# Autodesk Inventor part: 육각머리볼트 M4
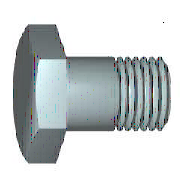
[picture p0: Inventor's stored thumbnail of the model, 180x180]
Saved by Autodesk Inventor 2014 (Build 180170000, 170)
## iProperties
IsCustomPart: 1
Created: 2012-02
Part Number: 육각머리볼트 M4
Material: 스테인리스강
Description: 6각 머리 볼트 및 6각 머리 나사
Document SubType Name: Modeling
Standard: KS B 1002
Designer: mduedu
Standards Organization: KS
Language: ko-KR
Size Designation: A + B M4 x 10
Categories: <MemberInstance><Categories><Category DisplayName="조임쇠" InternalName="e4da775c-781d-43d5-af7c-5136215cf5a6" Mnemonic="FSTN"><Category DisplayName="볼트" InternalN
Density: 8.08 g/cm^3
Mass: 1.91435 g
Surface Area: 2.70732 cm^2
Volume: 0.236925 cm^3
Appearance: 반광택
Author: mduedu
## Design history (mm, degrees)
sketch "스케치1"
  geometry: L1 (0, 2.94)-(0, 2); L2 (2.1, 2)-(10, 2); L3 (10, 2)-(10, 0); L4 (10, 0)-(-0.4, 0); L5 (-2.48, 0)-(12.08, 0) reference; L6 (-0.4, 0)-(-0.4, 2.94); L7 (-0.4, 2.94)-(0, 2.94); L8 (2.1, 2)-(1.67, 2); L9 (1.67, 2)-(0, 2); L10 (0, -0.588)-(0, 3.528) reference
  constraints: 16 end point, 2 collinear, 2 perpendicular, 1 parallel
  dimensions: "d0" = 10 distance between parallel lines of L3 L1 (= NLG); "d1" = 7.9 distance from line of L2.start L3 (= GEL); "d2" = 4 diameter of L2 L4 (= GD); "d9" = 0.4001 distance between parallel lines of L6 L1 (computed from SD); "d10" = 5.88 diameter of L7 L4 (= SD2); "d13" = 0.42952 distance of L2.start L8.end (computed from GAL); "d14" = 4 diameter of L9 L4 (= BDM)
revolve "본체" sketch "스케치1" stored, may be unused: angle "d12" = 90 deg
sketch "스케치2"
  geometry: L1 (0, 4.041)-(3.5, 2.021); L2 (3.5, 2.021)-(3.5, -2.021); L3 (3.5, -2.021)-(0, -4.041); L4 (0, -4.041)-(-3.5, -2.021); L5 (-3.5, -2.021)-(-3.5, 2.021); L6 (-3.5, 2.021)-(0, 4.041); 2 further points
  constraints: 12 end point, 1 coincident, 1 vertical, 11 other
  dimensions: "d11" = 7 distance between parallel lines of L5 L2 (= SW)
extrude "머리" join sketch "스케치2" distance "d3" = 2.4 (= KOH - SD); taper "d4" = 0 deg
sketch "스케치4"
  geometry: L1 (-2.8, 3.5)-(-2.8, 4.041); L2 (-2.8, 4.041)-(-2.487, 4.041); L3 (-2.487, 4.041)-(-2.8, 3.5); L4 (-3.28, 0)-(0.08, 0) reference; L5 (-0.4, 4.041)-(-2.8, 4.041) reference; L6 (-2.8, 2.021)-(-2.8, 4.041) reference
  constraints: 6 end point, 2 collinear, 1 perpendicular, 1 vertical
  dimensions: "d5" = 30 deg angle of L3 L1 (= ANG1); "d19" = 7 diameter of L1.start L4 (= SW0)
revolve "모따기1" sketch "스케치4" stored, may be unused: angle "d21" = 90 deg
workplane "Work Plane1"
body "Solid1"
feature "스레드" dims "d15" = 7.9 (= GEL), "d16" = 0
chamfer "모따기2" distance "d6" = 0.42941 (= -0.5 x SPD + 0.5 x GD); stored, may be unused: second distance "d7" = 0.42952 (computed from GUL), angle "d55" = 45 deg
other parameters: "NLG" = 10 [user parameter; used in 1 equation term], "GD" = 4 (= NND) [user parameter; used in 2 equation terms], "BDM" = 4 (= NND) [user parameter; used in 1 equation term], "KOH" = 2.8 [user parameter; used in 1 equation term], "GEL" = 7.9 [user parameter; used in 2 equation terms], "SW" = 7 [user parameter; used in 3 equation terms], "SW0" = 7 (= SW) [user parameter; used in 1 equation term], "SPD" = 3.14117 (= NND - 1.2269 x PTC) [user parameter; used in 1 equation term], "SD2" = 5.88 (= SDH) [user parameter; used in 1 equation term], "SD" = 0.4 [user parameter; used in 2 equation terms], "ANG1" = 30 deg [user parameter; used in 1 equation term], "GAL" = 0.42941 (= 0.61345 x PTC) [user parameter; used in 1 equation term], "GUL" = 0.42941 (= 0.61345 x PTC) [user parameter; used in 1 equation term], "d8" = 0, "RR" = 0.2 [user parameter], "d57" = 0, "d58" = 0, "TPU" = 14.28571 (computed from PTC) [user parameter], "GD1" = 3.14117 (= THREADDIA - 1.2269 x PTC) [user parameter], "THREADDIA" = 4 [user parameter; used in 1 equation term], "SDH" = 5.88 [user parameter; used in 1 equation term], "SDHG" = 2.1 [user parameter], "TOA" = 30 deg [user parameter], "PTC" = 0.7 [user parameter; used in 5 equation terms], "NND" = 4 [user parameter; used in 3 equation terms], "E0" = 8.085 (= 1.155 x SW) [user parameter]
